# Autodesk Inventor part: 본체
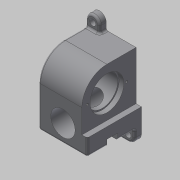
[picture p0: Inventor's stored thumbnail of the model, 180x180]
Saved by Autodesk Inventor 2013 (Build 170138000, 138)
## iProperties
Created: 2019-06
Part Number: 본체
Material: 일반
Document SubType Name: Modeling
Designer: mduedu
Density: 1 g/cm^3
Author: mduedu
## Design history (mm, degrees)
sketch "스케치1"
  geometry: L1 (37, 0)-(37, -43); L2 (37, -43)-(-60, -43); L3 (-60, -43)-(-60, 37); L4 (-60, 37)-(0, 37); A1 r 37 centre (0, 0) between (37, 0) and (0, 37); 1 further point
  constraints: 8 end point, 2 point on circle, 2 tangent, 1 centre point, 1 coincident, 1 horizontal, 1 parallel, 1 perpendicular, 1 vertical
  dimensions: "d0" = 37 radius of A1; "d2" = 80 distance of L2.end L3.end; "d3" = 97 distance of L1.end L2.end
extrude "돌출1" new body sketch "스케치1" stored distance "d4" = 72; taper "d5" = 0 deg
sketch "스케치2"
  geometry: L1 (72, 25)-(64, 25); L2 (64, 25)-(64, 97); L3 (64, 97)-(72, 97); L4 (72, 97)-(72, 25); L5 (72, 97)-(0, 97) reference; L6 (72, 60)-(72, 0) reference; 1 further point
  constraints: 8 end point, 2 collinear, 2 parallel, 1 horizontal, 1 perpendicular
  dimensions: "d6" = 72 distance between parallel lines of L1 L3; "d8" = 8 distance of L1.start L1.end
extrude "돌출2" cut sketch "스케치2" stored distance "d9" = 72; taper "d10" = 0 deg
sketch "스케치3"
  geometry: L1 (-36, -60)-(-36, 37) reference; L2 (-36, 37)-(28, 37) reference; L3 (28, 37)-(28, -35) reference; L4 (28, -35)-(36, -35) reference; L5 (36, -35)-(36, -60) reference; L6 (36, -60)-(-36, -60) reference; L7 (-36, 0)-(-19, 0); L8 (-19, 0)-(-19, 17.5); L9 (-19, 17.5)-(-36, 17.5); L10 (-36, 17.5)-(-36, 0); L11 (-19, 0)-(21, 0); L12 (21, 0)-(21, 23); L13 (21, 23)-(-19, 23); L14 (-19, 23)-(-19, 0); L15 (21, 0)-(28, 0); L16 (28, 0)-(28, 25); L17 (28, 25)-(21, 25); L18 (21, 25)-(21, 0); 1 further point
  constraints: 24 end point, 6 parallel, 3 horizontal, 3 perpendicular, 2 point on line, 1 horizontal alignment
  dimensions: "d11" = 7 distance of L16.end L17.end; "d13" = 47 distance between parallel lines of L3 L8; "d14" = 50 diameter of L17 L15; "d15" = 46 diameter of L13 L11; "d16" = 35 diameter of L9 L7
revolve "회전1" sketch "스케치3" stored, may be unused: angle "d17" = 90 deg
sketch "스케치4"
  geometry: C1 r 28 at (0, 0); 1 further point
  constraints: 1 centre point, 1 coincident
  dimensions: "d18" = 56 diameter of C1
extrude "돌출3" cut sketch "스케치4" distance "d19" = 2; taper "d20" = 0 deg
fillet "모깎기1" dims "d21" = 3
sketch "스케치5"
  geometry: C1 r 18 at (36, 26); 1 further point
  constraints: 1 centre point, 1 vertical alignment
  dimensions: "d22" = 36 diameter of C1; "d23" = 34 distance of C1.centre point (36, 60)
extrude "돌출4" cut sketch "스케치5" stored distance "d24" = 2; taper "d25" = 0 deg
sketch "스케치6"
  geometry: L1 (-37, -60)-(43, -60) reference; L2 (-8, -60)-(8, -60); L3 (8, -60)-(8, -51); L4 (8, -51)-(-8, -51); L5 (-8, -51)-(-8, -60); 2 further points
  constraints: 8 end point, 2 parallel, 1 horizontal, 1 midpoint, 1 perpendicular, 1 point on line, 1 vertical alignment
  dimensions: "d26" = 16 distance between parallel lines of L3 L5; "d28" = 9 distance between parallel lines of L1 L4
extrude "돌출5" cut sketch "스케치6" stored distance "d29" = 2; taper "d30" = 0 deg
sketch "스케치7"
  geometry: L1 (-10, -60)-(10, -60); L2 (10, -60)-(10, -48.967); L3 (10, -48.967)-(-10, -48.967); L4 (-10, -48.967)-(-10, -60); L5 (36, -60)-(-36, -60) reference; 3 further points
  constraints: 8 end point, 2 parallel, 1 collinear, 1 horizontal, 1 midpoint, 1 perpendicular, 1 vertical alignment, 2 other
  dimensions: "d31" = 20 distance of L2.end L3.end
extrude "돌출6" cut sketch "스케치7" stored distance "d33" = 2; taper "d34" = 0 deg
sketch "스케치8"
  geometry: L1 (0, 25)-(8, 25) reference; L2 (8, 25)-(8, 60) reference; L3 (72, 60)-(8, 60) reference; L4 (72, 0)-(72, 60) reference; L5 (72, 0)-(0, 0) reference; L6 (0, 25)-(0, 0) reference; L7 (72, 0)-(0, 0); L8 (0, 0)-(0, -20); L9 (0, -20)-(72, -20); L10 (72, -20)-(72, 0); C1 r 18 at (36, 26) reference; 1 further point
  constraints: 8 end point, 2 parallel, 1 horizontal, 1 perpendicular, 1 point on line
  dimensions: "d35" = 20 distance of L7.end L8.end
extrude "돌출7" join sketch "스케치8" distance "d37" = 10; taper "d38" = 0 deg
sketch "스케치9"
  geometry: L1 (0, -37)-(0, 0) reference; L2 (0, 0)-(64, 0) reference; L3 (64, -37)-(64, 0) reference; L4 (44, 0)-(64, 0); L5 (64, 0)-(64, 20); L6 (64, 20)-(44, 20); L7 (44, 20)-(44, 0); 1 further point
  constraints: 9 end point, 2 perpendicular, 1 horizontal, 1 parallel
  dimensions: "d39" = 20 distance of L2.end L5.end; "d51" = 20 distance of L5.end L6.end
extrude "돌출8" join sketch "스케치9" distance "d41" = 10; taper "d42" = 0 deg
fillet "모깎기2" dims "d43" = 10
sketch "스케치10"
  geometry: L1 (-62, -20)-(-10, -20) reference; L2 (0, -10)-(0, 0) reference; L3 (-72, 0)-(0, 0) reference; L4 (-72, 0)-(-72, -10) reference; C1 r 4.5 at (-62, -10); C2 r 4.5 at (-10, -10); A1 r 10 centre (-62, -10) between (-72, -10) and (-62, -20) reference; A2 r 10 centre (-10, -10) between (-10, -20) and (0, -10) reference; 1 further point
  constraints: 2 centre point, 2 coincident, 1 equal radius
  dimensions: "d44" = 9 diameter of C1
extrude "돌출9" cut sketch "스케치10" stored distance "d45" = 10; taper "d46" = 0 deg
sketch "스케치11"
  geometry: L1 (-64, 10)-(-64, 0) reference; L2 (-44, 0)-(-64, 0) reference; L3 (-44, 0)-(-44, 10) reference; C1 r 4.5 at (-54, 10); A1 r 10 centre (-54, 10) between (-44, 10) and (-64, 10) reference; 1 further point
  constraints: 1 centre point, 1 coincident
  dimensions: "d47" = 9 diameter of C1
extrude "돌출10" cut sketch "스케치11" stored distance "d48" = 10; taper "d49" = 0 deg
fillet "모깎기4" dims "d52" = 3
fillet "모깎기5" dims "d53" = 3
fillet "모깎기6" dims "d54" = 3
fillet "모깎기7" dims "d55" = 3
sketch "스케치12" dims "d56" = 58
  geometry: 3 further points
  constraints: 2 horizontal alignment, 1 coincident, 2 other
hole "구멍1" sketch "스케치12" at (66, 35) diameter "d57" = 3.242; stored, may be unused: countersink angle "d61" = 90 deg, drill point angle "d63" = 118 deg; dims "d58" = 10, "d59" = 4, "d60" = 2, "d62" = 12
sketch "스케치13" dims "d67" = 44
  geometry: 3 further points
  constraints: 2 vertical alignment, 1 coincident, 2 other
hole "구멍2" sketch "스케치13" at (0, 22) diameter "d68" = 3.242; stored, may be unused: countersink angle "d72" = 90 deg, drill point angle "d74" = 118 deg; dims "d69" = 10, "d70" = 4, "d71" = 2, "d73" = 12
sketch "스케치14"
  geometry: 3 further points
  constraints: 2 horizontal alignment
  dimensions: "d78" = 25 distance of point (11, 8) point (36, 8); "d79" = 25 distance of point (61, 8) point (36, 8)
hole "구멍3" sketch "스케치14" at (11, 8), (61, 8) diameter "d80" = 3.242; stored, may be unused: countersink angle "d84" = 90 deg, drill point angle "d86" = 118 deg; dims "d81" = 8, "d82" = 4, "d83" = 2, "d85" = 10
node "솔리드1"
pattern_circular "원형 패턴1" dims angle "d65" = 360 deg
pattern_circular "원형 패턴2" dims angle "d76" = 360 deg
node "투영된 루프1"
node "투영된 루프2"
node "투영된 루프3"
node "절단 모서리 투영1"
